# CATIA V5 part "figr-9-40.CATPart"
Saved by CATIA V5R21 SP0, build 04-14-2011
Part number: Part1
Bounding box of the stored display mesh (mm): x -40 to 40, y -20 to 191.034, z 0 to 131.919
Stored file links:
  D:\CATIA V5R21 E-RESOURCES\CATIA-V5R21\catia-v5r21-prt\c09-catia-v5r20-prt\c09-catia-v5r21-figr-9-40.CATPart
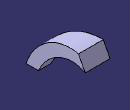
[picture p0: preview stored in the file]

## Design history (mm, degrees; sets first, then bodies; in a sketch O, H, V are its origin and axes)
Set1
  Plane1: type Normal, Curve Sketch2, RefPoint vertex of Sketch2
Body1 (main body)
  Sketch1 on xy-plane, origin (0, 0, 0), H (1, 0, 0), V (0, 1, 0)
    line L1 (20, 20) -> (20, -20)
    line L2 (20, -20) -> (-20, -20)
    line L3 (-20, -20) -> (-20, 20)
    line L4 (-20, 20) -> (20, 20)
    vertical: L1 V, L3 V
    horizontal: L2 H, L4 H
    equidistance: L1 L3 O, L2 L4 O
  Sketch2 on yz-plane, origin (0, 0, 0), H (0, 1, 0), V (0, 0, 1)
    spline S1 through (0, 0) (20, 60) (60, 80) (120, 90) (180, 110)
    point P1 (0, 0)
    coincidence: P1 O
  Sketch3 on Plane1, origin (0, 186.3865, 97.8327), H (1, 0, 0), V (0, -0.4648, 0.8854)
    point P1 (0, 13.7415)
    line L1 (40, 37.4831) -> (40, -10)
    line L2 (40, -10) -> (-40, -10)
    line L3 (-40, -10) -> (-40, 37.4831)
    line L4 (-40, 37.4831) -> (40, 37.4831)
    reference projected point E1 (0, 13.7415) from vertex of Sketch2
    coincidence: P1 V, P1 E1
    vertical: L1 V, L3 V
    horizontal: L2 H, L4 H
    equidistance: L1 L3 P1, L2 L4 P1
  Loft1: Sections (Sketch1; Sketch3)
